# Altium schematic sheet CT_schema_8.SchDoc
size 277 x 170 mm
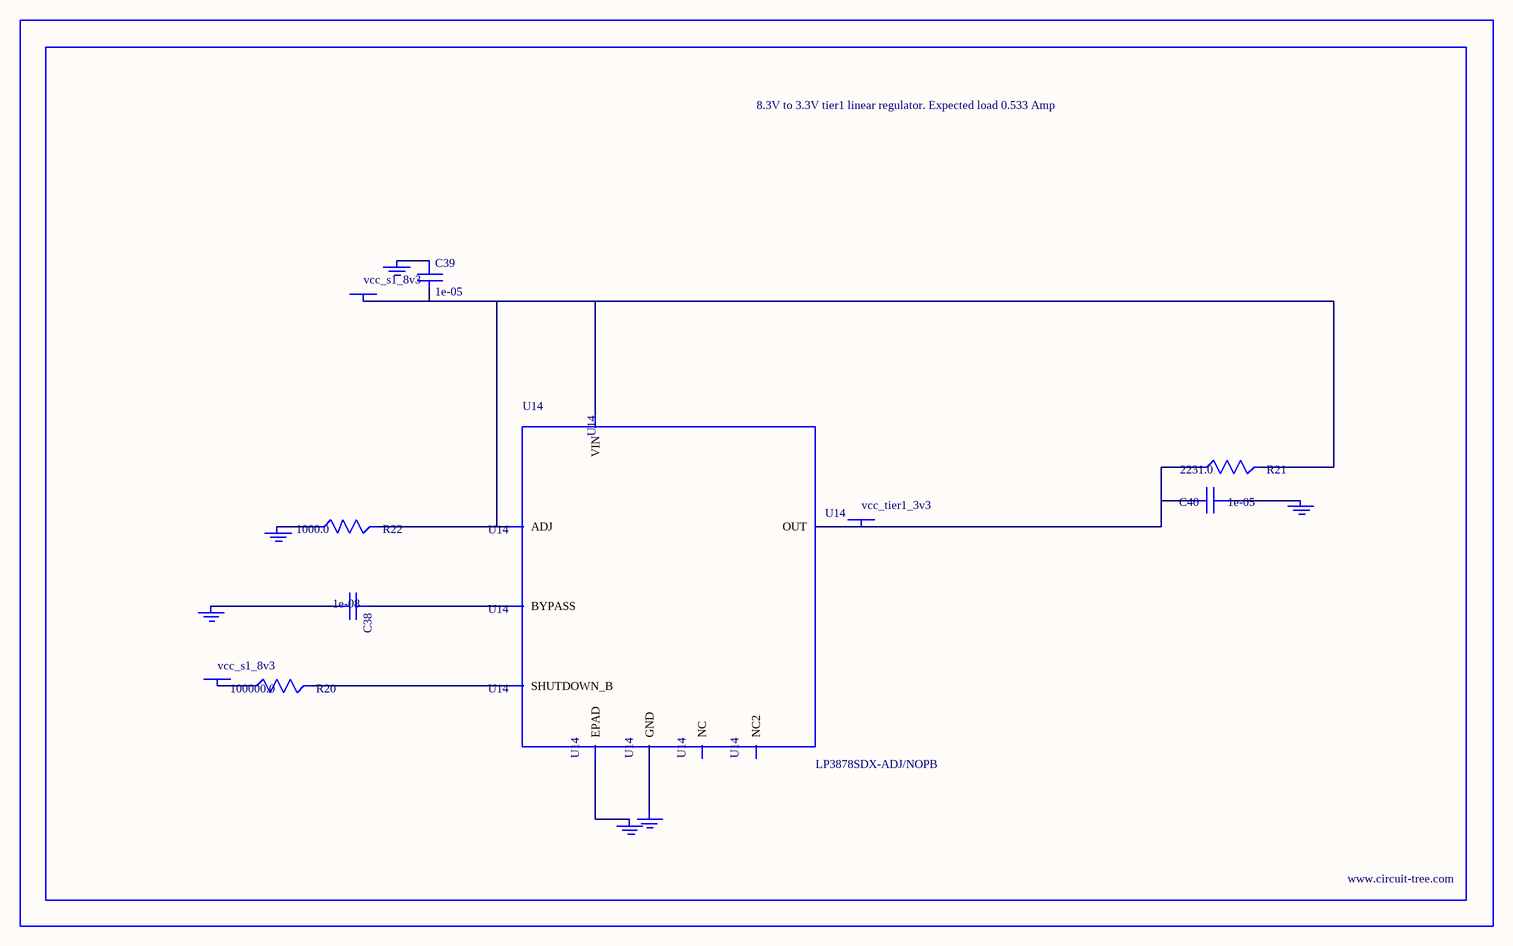
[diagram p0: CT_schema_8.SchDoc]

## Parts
BORDER7  (no value)
C38  1e-08  [C0402]
C39  1e-05  [C1206]
C40  1e-05  [C1210]
GND_INSTANCE_7_0  (no value)
GND_INSTANCE_7_1  (no value)
GND_INSTANCE_7_2  (no value)
GND_INSTANCE_7_3  (no value)
GND_INSTANCE_7_4  (no value)
GND_INSTANCE_7_5  (no value)
POWER_INSTANCE_7_0  vcc_s1_8v3
POWER_INSTANCE_7_1  vcc_s1_8v3
POWER_INSTANCE_7_2  vcc_tier1_3v3
R20  100000.0  [R0603]
R21  2231.0  [R0603]
R22  1000.0  [R0603]
U14  LP3878SDX-ADJ/NOPB  [WSON-8]

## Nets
NetC38_1: C38.1 U14.1(BYPASS)
NetC38_2: C38.2 GND_INSTANCE_7_0.0(GND)
NetC39_1: C39.1 GND_INSTANCE_7_1.0(GND)
NetC39_2: C39.2 POWER_INSTANCE_7_0.0(PWR) R21.2 R22.2 U14.4(VIN) U14.6(ADJ)
NetC40_1: C40.1 GND_INSTANCE_7_2.0(GND)
NetC40_2: C40.2 POWER_INSTANCE_7_2.0(PWR) R21.1 U14.5(OUT)
NetGND_INSTANCE_7_3_0: GND_INSTANCE_7_3.0(GND) R22.1
NetGND_INSTANCE_7_4_0: GND_INSTANCE_7_4.0(GND) U14.PAD(EPAD)
NetGND_INSTANCE_7_5_0: GND_INSTANCE_7_5.0(GND) U14.3(GND)
NetPOWER_INSTANCE_7_1_0: POWER_INSTANCE_7_1.0(PWR) R20.1
NetR20_2: R20.2 U14.8(SHUTDOWN_B)

Not connected (* = marked no-connect by the designer): U14 2(NC) 7(NC2)

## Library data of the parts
BORDER7 = BORDER_PAGE7
C38 = C0402C103K3RAC
C39 = C1206C106K3RACTU
C40 = GRM32DR61E106MA12L
GND_INSTANCE_7_0-GND_INSTANCE_7_5 = GND
POWER_INSTANCE_7_0-POWER_INSTANCE_7_2 = PWR
R20 = RC0603JR-07100KL
R21 = R21
R22 = RC0603JR-071KL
